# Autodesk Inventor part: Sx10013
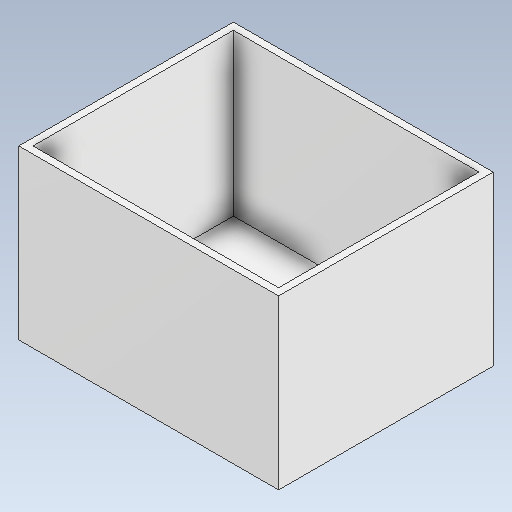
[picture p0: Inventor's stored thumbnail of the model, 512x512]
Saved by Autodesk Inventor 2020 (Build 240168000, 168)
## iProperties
Created: 2021-02
Part Number: Sx10013
Material: Generico
Document SubType Name: Modeling
Designer: zambolin
Density: 1 g/cm^3
Appearance: Default
Author: zambolin
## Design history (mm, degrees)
feature "Solido2"
node "Solido1"
